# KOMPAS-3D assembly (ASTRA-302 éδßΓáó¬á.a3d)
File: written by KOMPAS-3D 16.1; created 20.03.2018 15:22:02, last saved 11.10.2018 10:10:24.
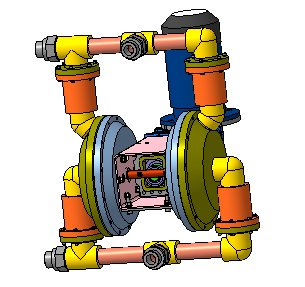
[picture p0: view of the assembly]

Expressions: A2-70; М6 x 50 - A2-70
Referenced files in Z:\Мембранные насосы\Мембранный электропривод\А302-00.00.000 - ASTRA-302 (МЭ200)\3Д\: А302-00.15.001 - Мембрана.a3d, А302-00.10.000 - Рабочая камера.a3d, А302-00.05.002 - Ловитель.m3d, А302-00.05.001 - Основание.m3d, Выставка - Основание.m3d, А302-00.35.000 - Фланец.a3d, А302-00.20.002 - Эксцентрик.m3d, А302-00.20.004 - Вал.m3d, А302-00.20.003 - Ползун.m3d
Referenced files in C:\Program Files\ASCON\KOMPAS-3D V16\Libs\PartLib\DATA\vault\Methods\Kompas\3D\: PLib_Washer_1_712.m3d, PLib_Washer_2_712.m3d, PLib_Screw_DIN_7984_1500.m3d, PLib_Check_spring_rings_GOST_13942_911.m3d, PLib_Key_prismatic_712.m3d
Referenced files in Z:\1 ПКИ 3D\Полипропиленовые фитинги, трубы\: Колено 90гр 40 FV PPR ф. FV PLAST.m3d, Тройник 40 FV PPR ф. FV PLAST.m3d, Переходник с пластмассовой резьбой наружной 40х1 1_4 FV PPR ф.FV Plast.m3d
Referenced files in Z:\1 ПКИ 3D\Полипропиленовые фитинги, трубы\Трубы\: Труба 40 PN10 S=3,7 FV PPR ф. FV PLAST.m3d
Referenced files in C:\Program Files\ASCON\KOMPAS-3D V16\Libs\PartLib\DATA\VAULT\Methods\kompas\3d\: PLib_Washer_2_712.m3d, PLib_Bolt_1_900.m3d, PLib_Nut_OST92_900.m3d
Referenced files in D:\3Д модели\Крепеж\: Гайка шестигранная самостопорящаяся с фланцем DIN 6927-M6 - A2-70.m3d
Referenced files in Z:\1 ПКИ 3D\1 Крепеж стандартный\Подшипник\: Подшипник радиально-упорный 80х40х18 7208 BEP SKF.m3d, Подшипниковый узел UCF207 ISB EcoLine.m3d, Подшипник 52х25х15 62052RSH SKF.m3d
Referenced files in Z:\Мембранные насосы\Мембранный электропривод\А302-00.00.000 - ASTRA-302 (МЭ200)\3Д ПВХ\Отработка\: Упор.m3d, Упор-1.m3d, Фиксатор.m3d
Referenced files in Z:\1 ПКИ 3D\Редуктора NMRW\Редукторы\: Червячный мотор-редуктор NMRV063 АИР80.a3d
Referenced files: graphic.tdp
Referenced files in \\192.168.87.28\Konstructor_doc\Мембранные насосы\Мембранный электропривод\А302-00.00.000 - ASTRA-302 (МЭ200)\Чертежи\: А302-00.05.002 - Ловитель.cdw, А302-00.05.001 - Основание.cdw, А302-00.35.000 - Фланец.cdw
Referenced files in Z:\Мембранные насосы\Мембранный электропривод\А302-00.00.000 - ASTRA-302 (МЭ200)\3Д ПВХ\: А302-01.05.012 - Фиксатор.cdw, А302-01.05.014 - Упор.cdw
Referenced files in Z:\Мембранные насосы\Мембранный электропривод\А302-00.00.000 - ASTRA-302 (МЭ200)\Чертежи\: А302-00.20.002 - Эксцентрик.cdw
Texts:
  (-) А302-00.15.000 Мембрана (1)
  (-) А302-00.15.000 Мембрана (2)
  Сталь 20 ГОСТ 1050-2013
  Шайба C 12.04.019 ГОСТ 6958-78
  Крепежное изделие ГОСТ
  (-) Шайба C 12.04.019 ГОСТ 6958-78 (1)
  (-) Шайба C 12.04.019 ГОСТ 6958-78 (2)
  (-) А302-00.10.000 Рабочая камера (1)
  (-) А302-00.10.000 Рабочая камера (2)
  Колено 90@1~ @2~40 FV PPR ф. "FV PLAST"
  (-) Колено 90гр 40 FV PPR ф. FV PLAST (1)
  Тройник @2~40 FV PPR ф. "FV PLAST"
  (-) Тройник 40 FV PPR ф. FV PLAST (1)
  (-) Тройник 40 FV PPR ф. FV PLAST (2)
  (-) Колено 90гр 40 FV PPR ф. FV PLAST (2)
  (-) Тройник 40 FV PPR ф. FV PLAST (3)
  (-) Тройник 40 FV PPR ф. FV PLAST (4)
  Труба 40 PN10 S=3,7 FV PPR ф. FV PLAST
  (-) Труба ф40х3,7 (PN10) FV PPR ф. FV PLAST (1)
  (-) Труба ф40х3,7 (PN10) FV PPR ф. FV PLAST (2)
  Переходник с пластмассовой резьбой
  наружной 40х1 1/4" FV PPR
  ф. "FV PLAST"
  Переходник с пластмассовой резьбой  / наружной 40х1 1/4" FV PPR  / ф. "FV PLAST"
  (-) Переходник с пластмассовой резьбой наружной 40х1 1/4" FV PPR ф."FV Plast" (1)
  (-) Труба ф40х3,7 (PN10) FV PPR ф. FV PLAST (3)
  (-) Труба ф40х3,7 (PN10) FV PPR ф. FV PLAST (4)
  (-) Переходник с пластмассовой резьбой наружной 40х1 1/4" FV PPR ф."FV Plast" (2)
  (-) Переходник с пластмассовой резьбой наружной 40х1 1/4" FV PPR ф."FV Plast" (3)
  (-) Переходник с пластмассовой резьбой наружной 40х1 1/4" FV PPR ф."FV Plast" (4)
  Сталь 12Х18Н10Т ГОСТ 5632-72
  Шайба C.6.21 ГОСТ 11371-78
  (-) Шайба C.6.21 ГОСТ 11371-78 (1)
  Сталь 30Х13 ГОСТ 5632-72
  Шайба 6 30Х13 019 ГОСТ 6402-70
  (-) Шайба 6 30Х13 019 ГОСТ 6402-70 (1)
  Винт с цилиндрической головкой и шестигранным углублением под ключ ГОСТ Р ИСО 4762 - М6 x 50 - A2-70
  Винт с цилиндрической головкой
  и шестигранным углублением под ключ
  ГОСТ Р ИСО  4762-М6 x 50-A2-70
  Винт с цилиндрической головкой и шестигранным углублением под ключ
  (-) Винт с цилиндрической головкой и шестигранным углублением под ключ ГОСТ Р ИСО 4762 - М6 x 50 - A2-70 (1)
  Гайка шестигранная самостопорящаяся
  с фланцем DIN 6927-M6-A2-70
  (-) Гайка шестигранная самостопорящаяся с фланцем DIN 6927-M6 - A2-70 (1)
  (-) Гайка шестигранная самостопорящаяся с фланцем DIN 6927-M6 - A2-70 (2)
  (-) Шайба C.6.21 ГОСТ 11371-78 (2)
  (-) Шайба 6 30Х13 019 ГОСТ 6402-70 (2)
  Винт с цилиндрической головкой и шестигранным углублением под ключ ГОСТ Р ИСО  4762-М6 x 50-A2-70
  (-) Винт с цилиндрической головкой и шестигранным углублением под ключ ГОСТ Р ИСО 4762 - М6 x 50 - A2-70 (2)
  (-) А302-00.05.002 Ловитель (1)
  (ф) А302-00.05.001 Основание (1)
  (-) А302-00.05.002 Ловитель (2)
  (ф) А302-00.05.001 Основание (2)
  Шайба C.8.21 ГОСТ 11371-78
  (-) Шайба C.8.21 ГОСТ 11371-78
  Шайба C 8.04.019 ГОСТ 6958-78
  (-) Шайба C 8.04.019 ГОСТ 6958-78
  Шайба 8 30Х13 019 ГОСТ 6402-70
  (-) Шайба 8 30Х13 019 ГОСТ 6402-70
  Болт М8-6gx30.58.019 ГОСТ 7805-70
  hole1
  hole2
  (-) Болт М8-6gx30.58.019 ГОСТ 7805-70
  Гайка М8-6H.5.019 ГОСТ 5915-70
  bcut1
  hcut1
  cut1
  (-) Гайка М8-6H.5.019 ГОСТ 5915-70
  Подшипник радиально-упорный 80х40х18 7208 BEP SKF
  (-) Подшипник радиально-упорный 80х40х18 7208 BEP SKF
  Подшипниковый узел UCF207 ISB EcoLine
  (-) Подшипниковый узел UCF207 ISB EcoLine
  (-) А302-01.05.012 Фиксатор
  (-) А302-01.05.014 Упор
  NMRV063 N P(кВт) V5
  P(мощн./дв.), i(передат. отн.) см. заказ
  Мотор-редуктор / NMRV063 N P(кВт) V5 / P(мощн./дв.), i(передат. отн.) см. заказ
  Двигатель1400 об/минN=1400/i
  (ф) Червячный мотор-редуктор NMRV063 АИР80
  (ф) А302-00.20.001 Основание
  (ф) А302-00.35.000 Фланец
  (-) А302-00.20.002 Эксцентрик
  Сталь 65Г ГОСТ 14959-79
  Кольцо A25.65Г ГОСТ 13942-86
  Isp3
  (-) Кольцо A25.65Г ГОСТ 13942-86
  Подшипник 52х25х15 62052RSH SKF
  (-) Подшипник 52х25х15 62052RSH SKF
  (-) А302-00.20.004 Вал
  (-) А302-00.20.003 Ползун
  Шайба C.5.04.019 ГОСТ 11371-78
  (-) Шайба C.5.04.019 ГОСТ 11371-78
  Болт М5-6gx35.58.019 ГОСТ 7805-70
  (-) Болт М5-6gx35.58.019 ГОСТ 7805-70
  Шайба 5 30Х13 019 ГОСТ 6402-70
  (-) Шайба 5 30Х13 019 ГОСТ 6402-70
  Гайка М5-6H.5.019 ГОСТ 5915-70
  (-) Гайка М5-6H.5.019 ГОСТ 5915-70
  Шайба C.8.04.019 ГОСТ 11371-78
  (-) Шайба C.8.04.019 ГОСТ 11371-78
  Винт с цилиндрической головкой и шестигранным углублением под ключ ГОСТ Р ИСО 4762 - М8 x 20 - 6.8 - A9J
  (-) Винт с цилиндрической головкой и шестигранным углублением под ключ ГОСТ Р ИСО 4762 - М8 x 20 - 6.8 - A9J
  Винт с цилиндрической головкой и шестигранным углублением под ключ ГОСТ Р ИСО 4762 - М8 x 35 - 6.8 - A9J
  (-) Винт с цилиндрической головкой и шестигранным углублением под ключ ГОСТ Р ИСО 4762 - М8 x 35 - 6.8 - A9J
  Шпонка 8x7x90 ГОСТ 23360-78
  skr2
  skr1
  Шпонка 8 x 7 x 90 ГОСТ 23360-78
  (-) Шпонка 8x7x90 ГОСТ 23360-78
  ГОСТ 6958-78
  ГОСТ 11371-78
  ГОСТ 6402-70
  ГОСТ Р ИСО 4762-2012
  ГОСТ 7805-70
  М8-6gx30.58.019
  ГОСТ 5915-70
  ГОСТ 13942-86
  М5-6gx35.58.019
  ГОСТ 23360-78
